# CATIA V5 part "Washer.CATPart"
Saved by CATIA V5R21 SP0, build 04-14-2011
Part number: washer
Bounding box of the stored display mesh (mm): x -24 to 24, y -23.825 to 23.825, z 0 to 3
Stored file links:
  D:\CATIA V5R21 E-RESOURCES\CATIA-V5R21\catia-v5r21-Prts\c14_catia_v5r21_prt\c14-catia-v5r21-figr-14-26 & 27\Part & Asm\Washer.CATPart
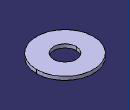
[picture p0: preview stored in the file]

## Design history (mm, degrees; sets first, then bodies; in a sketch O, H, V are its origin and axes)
Body1 (main body)
  Sketch1 on xy-plane, origin (0, 0, 0), H (1, 0, 0), V (0, 1, 0)
    circle A1 centre (0, 0) radius 24
    circle A2 centre (0, 0) radius 9.5
    radius A1 = 24
    radius A2 = 9.5
  Pad1: profile Sketch1, direction (0, 0, 1), length 3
